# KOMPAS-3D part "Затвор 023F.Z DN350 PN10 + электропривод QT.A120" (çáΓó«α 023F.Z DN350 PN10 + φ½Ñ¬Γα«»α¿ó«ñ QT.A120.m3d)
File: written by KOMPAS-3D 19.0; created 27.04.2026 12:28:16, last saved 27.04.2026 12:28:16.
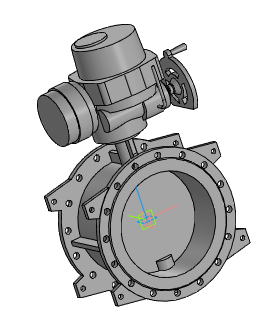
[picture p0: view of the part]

Document properties: Полное имя файла: Затвор 023F.Z DN350 PN10 + электропривод QT.A120.a3d

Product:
- Part/product: Затвор 023F.Z DN350 PN10 + электропривод QT.A120
    Масса: 251.374

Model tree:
1. Операция без истории:1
